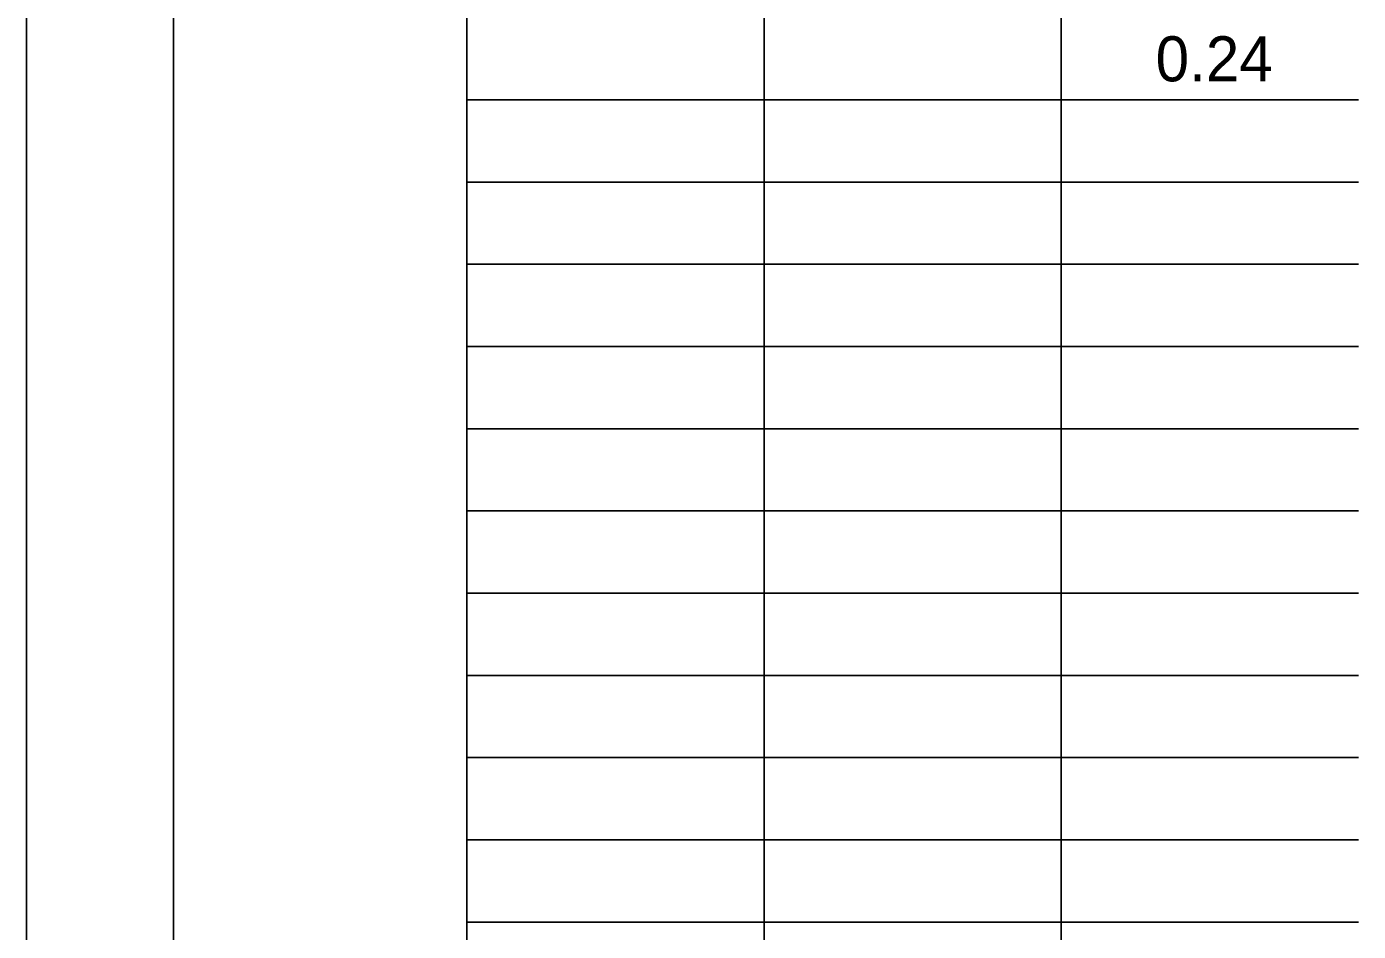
# Model space of a CAD drawing. Extents: x 0 to 34, y 0 to 22.
# Drawn here: x 0 to 4.537, y 15.868 to 18.949 of the extents above; entities that cross this region are included whole.
import ezdxf

# ---------------------------------------------------------------- set-up
doc = ezdxf.new("R2010")
doc.units = 0
for name, color, linetype in [('SH_Border', 7, 'Continuous'), ('SH_Cut_Line', 7, 'Continuous'), ('SH_Text', 7, 'Continuous')]:
    doc.layers.add(name, color=color, linetype=linetype)

msp = doc.modelspace()

# ---------------------------------------------------------------- linework, layer by layer
at = {"layer": 'SH_Border'}
for points in [[(0.5, 21.5), (1.5, 21.5), (1.5, 0.5), (0.5, 0.5)], [(1.5, 21.5), (33.5, 21.5), (33.5, 0.5), (1.5, 0.5)]]:
    msp.add_lwpolyline(points, close=True, dxfattribs=at)
at = {"layer": 'SH_Cut_Line'}
msp.add_lwpolyline([(0, 0), (34, 0), (34, 22), (0, 22)], close=True, dxfattribs=at)
at = {"layer": 'SH_Text'}
for p, q in [((1.5, 20.1), (1.5, 18.7)), ((2.5123, 20.1), (2.5123, 18.7)), ((3.5247, 20.1), (3.5247, 18.7)), ((1.5, 18.7), (2.5123, 18.7)), ((1.5, 18.7), (1.5, 18.14)), ((2.5123, 18.7), (3.5247, 18.7)), ((2.5123, 18.7), (2.5123, 18.14)), ((3.5247, 18.7), (4.537, 18.7)), ((3.5247, 18.7), (3.5247, 18.14)), ((1.5, 18.42), (2.5123, 18.42)), ((2.5123, 18.42), (3.5247, 18.42)), ((3.5247, 18.42), (4.537, 18.42)), ((1.5, 18.14), (2.5123, 18.14)), ((1.5, 18.14), (1.5, 17.86)), ((2.5123, 18.14), (3.5247, 18.14)), ((2.5123, 18.14), (2.5123, 17.86)), ((3.5247, 18.14), (4.537, 18.14)), ((3.5247, 18.14), (3.5247, 17.86)), ((1.5, 17.86), (2.5123, 17.86)), ((1.5, 17.86), (1.5, 17.58)), ((2.5123, 17.86), (3.5247, 17.86)), ((2.5123, 17.86), (2.5123, 17.58)), ((3.5247, 17.86), (4.537, 17.86)), ((3.5247, 17.86), (3.5247, 17.58)), ((1.5, 17.58), (2.5123, 17.58)), ((1.5, 17.58), (1.5, 17.3)), ((2.5123, 17.58), (3.5247, 17.58)), ((2.5123, 17.58), (2.5123, 17.3)), ((3.5247, 17.58), (4.537, 17.58)), ((3.5247, 17.58), (3.5247, 17.3)), ((1.5, 17.3), (2.5123, 17.3)), ((1.5, 17.3), (1.5, 17.02)), ((2.5123, 17.3), (3.5247, 17.3)), ((2.5123, 17.3), (2.5123, 17.02)), ((3.5247, 17.3), (4.537, 17.3)), ((3.5247, 17.3), (3.5247, 17.02)), ((1.5, 17.02), (2.5123, 17.02)), ((1.5, 17.02), (1.5, 16.74)), ((2.5123, 17.02), (3.5247, 17.02)), ((2.5123, 17.02), (2.5123, 16.74)), ((3.5247, 17.02), (4.537, 17.02)), ((3.5247, 17.02), (3.5247, 16.74)), ((1.5, 16.74), (2.5123, 16.74)), ((1.5, 16.74), (1.5, 16.18)), ((2.5123, 16.74), (3.5247, 16.74)), ((2.5123, 16.74), (2.5123, 16.18)), ((3.5247, 16.74), (4.537, 16.74)), ((3.5247, 16.74), (3.5247, 16.18)), ((1.5, 16.46), (2.5123, 16.46)), ((2.5123, 16.46), (3.5247, 16.46)), ((3.5247, 16.46), (4.537, 16.46)), ((1.5, 16.18), (2.5123, 16.18)), ((1.5, 16.18), (1.5, 15.9)), ((2.5123, 16.18), (3.5247, 16.18)), ((2.5123, 16.18), (2.5123, 15.9)), ((3.5247, 16.18), (4.537, 16.18)), ((3.5247, 16.18), (3.5247, 15.9)), ((1.5, 15.9), (2.5123, 15.9)), ((1.5, 15.9), (1.5, 15.62)), ((2.5123, 15.9), (3.5247, 15.9)), ((2.5123, 15.9), (2.5123, 15.62)), ((3.5247, 15.9), (4.537, 15.9)), ((3.5247, 15.9), (3.5247, 15.62))]:
    msp.add_line(p, q, dxfattribs=at)

# ---------------------------------------------------------------- texts
msp.add_text('0.24', height=0.15333, dxfattribs=at).set_placement((3.8463, 18.7633))

doc.saveas('drawing.dxf')
